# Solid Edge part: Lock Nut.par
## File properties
Author: Sarvanan
Template: sync iso part.par
Last saved by: CADCIM
Revision: 8
Application: Solid Edge
Accuracy: 0.990
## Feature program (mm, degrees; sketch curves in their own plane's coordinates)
sketch for "Hole_1" plane through (21.0838, 43.6973, 8) normal (0, 0, 1) x-axis (1, 0, 0)
  hole centre (-1.3414, 0.2221) bore radius 6
hole "Hole_1" diameter 12 through
pattern "unnamed Pattern 1" of "Hole_1"
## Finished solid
Body 1: solid body, 21 faces, 56 edges, 36 vertices.
  Faces by surface: spun 12, plane 8, cylinder 1
  Edges by curve: circle 21, line 18, intersection 17
Bounding box of the edges (mm; curved faces can reach further): 30.022 x 26.000 x 8.000, from (4.7313, 30.9194, 0) to (34.7535, 56.9194, 8).
Cylindrical faces by radius (mm): R6 x1
Planar faces by outward normal: +y 1, +z 1, -y 1, -z 1, oblique 4
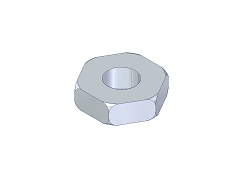
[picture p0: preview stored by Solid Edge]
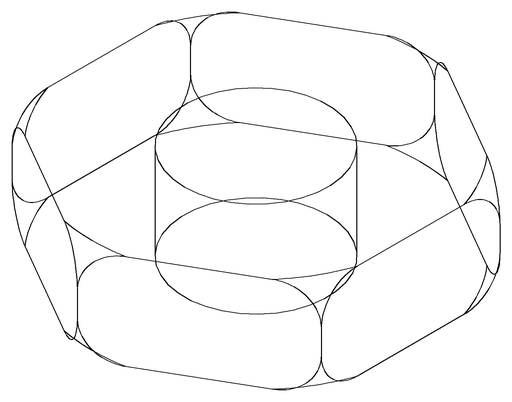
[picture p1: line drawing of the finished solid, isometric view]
